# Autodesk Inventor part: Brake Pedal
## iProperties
Shininess: 100.0
Angle Display Precision: 2
Document Length Units: 11269
Document Angle Units: 11279
Document Time Units: 11290
Document Mass Units: 11283
Document Length Units Precision: 3
Document Angle Units Precision: 2
Compacted: True
Created: 2001-08
Part Number: Brake Pedal
Document SubType Name: Modeling
Designer: Martin Budgell
Density: 0.0
Volumn: 0.0
Area: 0.0
PropertySet Name: Model Information
Control State: 0
Master: False
Checked Out: False
Author: Martin Budgell
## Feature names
1. Extrusion1
2. Sweep1
3. Extrusion3
4. Fillet1
5. Extrusion4
6. Fillet2
7. Fillet3
8. Extrusion5
9. Chamfer1
10. Extrusion6
11. Fillet4
12. Fillet5
13. Fillet6
14. Sweep2
15. Fillet7
